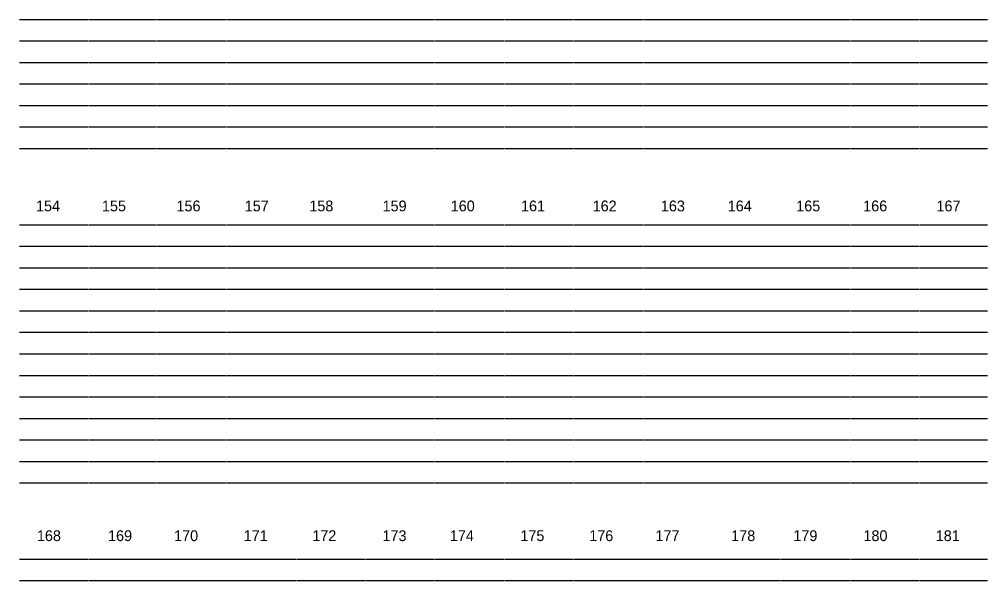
# Model space of a CAD drawing. Extents: x 11193 to 12507, y 10092 to 10555.
# Drawn here: x 11448.5 to 11643.4, y 10207.5 to 10320.5 of the extents above; entities that cross this region are included whole.
import ezdxf

# ---------------------------------------------------------------- set-up
doc = ezdxf.new("R2010")
doc.units = 0
doc.layers.add('Level 2', color=7, linetype='Continuous')

msp = doc.modelspace()

# ---------------------------------------------------------------- linework, layer by layer
at = {"layer": 'Level 2'}
for p, q in [((11448.48, 10320.47), (11462.41, 10320.47)), ((11462.53, 10320.47), (11476.09, 10320.47)), ((11476.2, 10320.47), (11490.17, 10320.47)), ((11490.29, 10320.47), (11504.25, 10320.47)), ((11504.37, 10320.47), (11518.14, 10320.47)), ((11518.25, 10320.47), (11532.02, 10320.47)), ((11532.12, 10320.47), (11546.1, 10320.47)), ((11546.2, 10320.47), (11559.98, 10320.47)), ((11560.08, 10320.47), (11574.07, 10320.47)), ((11574.17, 10320.47), (11587.94, 10320.47)), ((11588.04, 10320.47), (11601.62, 10320.47)), ((11601.72, 10320.47), (11615.7, 10320.47)), ((11615.8, 10320.47), (11629.58, 10320.47)), ((11629.69, 10320.47), (11643.42, 10320.47)), ((11448.48, 10316.13), (11462.41, 10316.13)), ((11462.53, 10316.13), (11476.09, 10316.13)), ((11476.2, 10316.13), (11490.17, 10316.13)), ((11490.29, 10316.13), (11504.25, 10316.13)), ((11504.37, 10316.13), (11518.14, 10316.13)), ((11518.25, 10316.13), (11532.02, 10316.13)), ((11532.12, 10316.13), (11546.1, 10316.13)), ((11546.2, 10316.13), (11559.98, 10316.13)), ((11560.08, 10316.13), (11574.07, 10316.13)), ((11574.17, 10316.13), (11587.94, 10316.13)), ((11588.04, 10316.13), (11601.62, 10316.13)), ((11601.72, 10316.13), (11615.7, 10316.13)), ((11615.8, 10316.13), (11629.58, 10316.13)), ((11629.69, 10316.13), (11643.42, 10316.13)), ((11448.48, 10311.8), (11462.41, 10311.8)), ((11462.53, 10311.8), (11476.09, 10311.8)), ((11476.2, 10311.8), (11490.17, 10311.8)), ((11490.29, 10311.8), (11504.25, 10311.8)), ((11504.37, 10311.8), (11518.14, 10311.8)), ((11518.25, 10311.8), (11532.02, 10311.8)), ((11532.12, 10311.8), (11546.1, 10311.8)), ((11546.2, 10311.8), (11559.98, 10311.8)), ((11560.08, 10311.8), (11574.07, 10311.8)), ((11574.17, 10311.8), (11587.94, 10311.8)), ((11588.04, 10311.8), (11601.62, 10311.8)), ((11601.72, 10311.8), (11615.7, 10311.8)), ((11615.8, 10311.8), (11629.58, 10311.8)), ((11629.69, 10311.8), (11643.42, 10311.8)), ((11448.48, 10307.47), (11462.41, 10307.47)), ((11462.53, 10307.47), (11476.09, 10307.47)), ((11476.2, 10307.47), (11490.17, 10307.47)), ((11490.29, 10307.47), (11504.25, 10307.47)), ((11504.37, 10307.47), (11518.14, 10307.47)), ((11518.25, 10307.47), (11532.02, 10307.47)), ((11532.12, 10307.47), (11546.1, 10307.47)), ((11546.2, 10307.47), (11559.98, 10307.47)), ((11560.08, 10307.47), (11574.07, 10307.47)), ((11574.17, 10307.47), (11587.94, 10307.47)), ((11588.04, 10307.47), (11601.62, 10307.47)), ((11601.72, 10307.47), (11615.7, 10307.47)), ((11615.8, 10307.47), (11629.58, 10307.47)), ((11629.69, 10307.47), (11643.42, 10307.47)), ((11448.48, 10303.14), (11462.41, 10303.14)), ((11462.53, 10303.14), (11476.09, 10303.14)), ((11476.2, 10303.14), (11490.17, 10303.14)), ((11490.29, 10303.14), (11504.25, 10303.14)), ((11504.37, 10303.14), (11518.14, 10303.14)), ((11518.25, 10303.14), (11532.02, 10303.14)), ((11532.12, 10303.14), (11546.1, 10303.14)), ((11546.2, 10303.14), (11559.98, 10303.14)), ((11560.08, 10303.14), (11574.07, 10303.14)), ((11574.17, 10303.14), (11587.94, 10303.14)), ((11588.04, 10303.14), (11601.62, 10303.14)), ((11601.72, 10303.14), (11615.7, 10303.14)), ((11615.8, 10303.14), (11629.58, 10303.14)), ((11629.69, 10303.14), (11643.42, 10303.14)), ((11448.48, 10298.81), (11462.41, 10298.81)), ((11462.53, 10298.81), (11476.09, 10298.81)), ((11476.2, 10298.81), (11490.17, 10298.81)), ((11490.29, 10298.81), (11504.25, 10298.81)), ((11504.37, 10298.81), (11518.14, 10298.81)), ((11518.25, 10298.81), (11532.02, 10298.81)), ((11532.12, 10298.81), (11546.1, 10298.81)), ((11546.2, 10298.81), (11559.98, 10298.81)), ((11560.08, 10298.81), (11574.07, 10298.81)), ((11574.17, 10298.81), (11587.94, 10298.81)), ((11588.04, 10298.81), (11601.62, 10298.81)), ((11601.72, 10298.81), (11615.7, 10298.81)), ((11615.8, 10298.81), (11629.58, 10298.81)), ((11629.69, 10298.81), (11643.42, 10298.81)), ((11448.48, 10294.47), (11462.41, 10294.47)), ((11462.53, 10294.47), (11476.09, 10294.47)), ((11476.2, 10294.47), (11490.17, 10294.47)), ((11490.29, 10294.47), (11504.25, 10294.47)), ((11504.37, 10294.47), (11518.14, 10294.47)), ((11518.25, 10294.47), (11532.02, 10294.47)), ((11532.12, 10294.47), (11546.1, 10294.47)), ((11546.2, 10294.47), (11559.98, 10294.47)), ((11560.08, 10294.47), (11574.07, 10294.47)), ((11574.17, 10294.47), (11587.94, 10294.47)), ((11588.04, 10294.47), (11601.62, 10294.47)), ((11601.72, 10294.47), (11615.7, 10294.47)), ((11615.8, 10294.47), (11629.58, 10294.47)), ((11629.69, 10294.47), (11643.42, 10294.47)), ((11448.48, 10279.14), (11462.41, 10279.14)), ((11462.53, 10279.14), (11476.09, 10279.14)), ((11476.2, 10279.14), (11490.17, 10279.14)), ((11490.29, 10279.14), (11504.25, 10279.14)), ((11504.37, 10279.14), (11518.14, 10279.14)), ((11518.25, 10279.14), (11532.02, 10279.14)), ((11532.12, 10279.14), (11546.1, 10279.14)), ((11546.2, 10279.14), (11559.98, 10279.14)), ((11560.08, 10279.14), (11574.07, 10279.14)), ((11574.17, 10279.14), (11587.94, 10279.14)), ((11588.04, 10279.14), (11601.62, 10279.14)), ((11601.72, 10279.14), (11615.7, 10279.14)), ((11615.8, 10279.14), (11629.58, 10279.14)), ((11629.69, 10279.14), (11643.42, 10279.14)), ((11448.48, 10274.81), (11462.41, 10274.81)), ((11462.53, 10274.81), (11476.09, 10274.81)), ((11476.2, 10274.81), (11490.17, 10274.81)), ((11490.29, 10274.81), (11504.25, 10274.81)), ((11504.37, 10274.81), (11518.14, 10274.81)), ((11518.25, 10274.81), (11532.02, 10274.81)), ((11532.12, 10274.81), (11546.1, 10274.81)), ((11546.2, 10274.81), (11559.98, 10274.81)), ((11560.08, 10274.81), (11574.07, 10274.81)), ((11574.17, 10274.81), (11587.94, 10274.81)), ((11588.04, 10274.81), (11601.62, 10274.81)), ((11601.72, 10274.81), (11615.7, 10274.81)), ((11615.8, 10274.81), (11629.58, 10274.81)), ((11629.69, 10274.81), (11643.42, 10274.81)), ((11448.48, 10270.48), (11462.41, 10270.48)), ((11462.53, 10270.48), (11476.09, 10270.48)), ((11476.2, 10270.48), (11490.17, 10270.48)), ((11490.29, 10270.48), (11504.25, 10270.48)), ((11504.37, 10270.48), (11518.14, 10270.48)), ((11518.25, 10270.48), (11532.02, 10270.48)), ((11532.12, 10270.48), (11546.1, 10270.48)), ((11546.2, 10270.48), (11559.98, 10270.48)), ((11560.08, 10270.48), (11574.07, 10270.48)), ((11574.17, 10270.48), (11587.94, 10270.48)), ((11588.04, 10270.48), (11601.62, 10270.48)), ((11601.72, 10270.48), (11615.7, 10270.48)), ((11615.8, 10270.48), (11629.58, 10270.48)), ((11629.69, 10270.48), (11643.42, 10270.48)), ((11448.48, 10266.14), (11462.41, 10266.14)), ((11462.53, 10266.14), (11476.09, 10266.14)), ((11476.2, 10266.14), (11490.17, 10266.14)), ((11490.29, 10266.14), (11504.25, 10266.14)), ((11504.37, 10266.14), (11518.14, 10266.14)), ((11518.25, 10266.14), (11532.02, 10266.14)), ((11532.12, 10266.14), (11546.1, 10266.14)), ((11546.2, 10266.14), (11559.98, 10266.14)), ((11560.08, 10266.14), (11574.07, 10266.14)), ((11574.17, 10266.14), (11587.94, 10266.14)), ((11588.04, 10266.14), (11601.62, 10266.14)), ((11601.72, 10266.14), (11615.7, 10266.14)), ((11615.8, 10266.14), (11629.58, 10266.14)), ((11629.69, 10266.14), (11643.42, 10266.14)), ((11448.48, 10261.81), (11462.41, 10261.81)), ((11462.53, 10261.81), (11476.09, 10261.81)), ((11476.2, 10261.81), (11490.17, 10261.81)), ((11490.29, 10261.81), (11504.25, 10261.81)), ((11504.37, 10261.81), (11518.14, 10261.81)), ((11518.25, 10261.81), (11532.02, 10261.81)), ((11532.12, 10261.81), (11546.1, 10261.81)), ((11546.2, 10261.81), (11559.98, 10261.81)), ((11560.08, 10261.81), (11574.07, 10261.81)), ((11574.17, 10261.81), (11587.94, 10261.81)), ((11588.04, 10261.81), (11601.62, 10261.81)), ((11601.72, 10261.81), (11615.7, 10261.81)), ((11615.8, 10261.81), (11629.58, 10261.81)), ((11629.69, 10261.81), (11643.42, 10261.81)), ((11448.48, 10257.48), (11462.41, 10257.48)), ((11462.53, 10257.48), (11476.09, 10257.48)), ((11476.2, 10257.48), (11490.17, 10257.48)), ((11490.29, 10257.48), (11504.25, 10257.48)), ((11504.37, 10257.48), (11518.14, 10257.48)), ((11518.25, 10257.48), (11532.02, 10257.48)), ((11532.12, 10257.48), (11546.1, 10257.48)), ((11546.2, 10257.48), (11559.98, 10257.48)), ((11560.08, 10257.48), (11574.07, 10257.48)), ((11574.17, 10257.48), (11587.94, 10257.48)), ((11588.04, 10257.48), (11601.62, 10257.48)), ((11601.72, 10257.48), (11615.7, 10257.48)), ((11615.8, 10257.48), (11629.58, 10257.48)), ((11629.69, 10257.48), (11643.42, 10257.48)), ((11448.48, 10253.15), (11462.41, 10253.15)), ((11462.53, 10253.15), (11476.09, 10253.15)), ((11476.2, 10253.15), (11490.17, 10253.15)), ((11490.29, 10253.15), (11504.25, 10253.15)), ((11504.37, 10253.15), (11518.14, 10253.15)), ((11518.25, 10253.15), (11532.02, 10253.15)), ((11532.12, 10253.15), (11546.1, 10253.15)), ((11546.2, 10253.15), (11559.98, 10253.15)), ((11560.08, 10253.15), (11574.07, 10253.15)), ((11574.17, 10253.15), (11587.94, 10253.15)), ((11588.04, 10253.15), (11601.62, 10253.15)), ((11601.72, 10253.15), (11615.7, 10253.15)), ((11615.8, 10253.15), (11629.58, 10253.15)), ((11629.69, 10253.15), (11643.42, 10253.15)), ((11448.48, 10248.82), (11462.41, 10248.82)), ((11462.53, 10248.82), (11476.09, 10248.82)), ((11476.2, 10248.82), (11490.17, 10248.82)), ((11490.29, 10248.82), (11504.25, 10248.82)), ((11504.37, 10248.82), (11518.14, 10248.82)), ((11518.25, 10248.82), (11532.02, 10248.82)), ((11532.12, 10248.82), (11546.1, 10248.82)), ((11546.2, 10248.82), (11559.98, 10248.82)), ((11560.08, 10248.82), (11574.07, 10248.82)), ((11574.17, 10248.82), (11587.94, 10248.82)), ((11588.04, 10248.82), (11601.62, 10248.82)), ((11601.72, 10248.82), (11615.7, 10248.82)), ((11615.8, 10248.82), (11629.58, 10248.82)), ((11629.69, 10248.82), (11643.42, 10248.82)), ((11448.48, 10244.48), (11462.41, 10244.48)), ((11462.53, 10244.48), (11476.09, 10244.48)), ((11476.2, 10244.48), (11490.17, 10244.48)), ((11490.29, 10244.48), (11504.25, 10244.48)), ((11504.37, 10244.48), (11518.14, 10244.48)), ((11518.25, 10244.48), (11532.02, 10244.48)), ((11532.12, 10244.48), (11546.1, 10244.48)), ((11546.2, 10244.48), (11559.98, 10244.48)), ((11560.08, 10244.48), (11574.07, 10244.48)), ((11574.17, 10244.48), (11587.94, 10244.48)), ((11588.04, 10244.48), (11601.62, 10244.48)), ((11601.72, 10244.48), (11615.7, 10244.48)), ((11615.8, 10244.48), (11629.58, 10244.48)), ((11629.69, 10244.48), (11643.42, 10244.48)), ((11448.48, 10240.15), (11462.41, 10240.15)), ((11462.53, 10240.15), (11476.09, 10240.15)), ((11476.2, 10240.15), (11490.17, 10240.15)), ((11490.29, 10240.15), (11504.25, 10240.15)), ((11504.37, 10240.15), (11518.14, 10240.15)), ((11518.25, 10240.15), (11532.02, 10240.15)), ((11532.12, 10240.15), (11546.1, 10240.15)), ((11546.2, 10240.15), (11559.98, 10240.15)), ((11560.08, 10240.15), (11574.07, 10240.15)), ((11574.17, 10240.15), (11587.94, 10240.15)), ((11588.04, 10240.15), (11601.62, 10240.15)), ((11601.72, 10240.15), (11615.7, 10240.15)), ((11615.8, 10240.15), (11629.58, 10240.15)), ((11629.69, 10240.15), (11643.42, 10240.15)), ((11448.48, 10235.82), (11462.41, 10235.82)), ((11462.53, 10235.82), (11476.09, 10235.82)), ((11476.2, 10235.82), (11490.17, 10235.82)), ((11490.29, 10235.82), (11504.25, 10235.82)), ((11504.37, 10235.82), (11518.14, 10235.82)), ((11518.25, 10235.82), (11532.02, 10235.82)), ((11532.12, 10235.82), (11546.1, 10235.82)), ((11546.2, 10235.82), (11559.98, 10235.82)), ((11560.08, 10235.82), (11574.07, 10235.82)), ((11574.17, 10235.82), (11587.94, 10235.82)), ((11588.04, 10235.82), (11601.62, 10235.82)), ((11601.72, 10235.82), (11615.7, 10235.82)), ((11615.8, 10235.82), (11629.58, 10235.82)), ((11629.69, 10235.82), (11643.42, 10235.82)), ((11448.48, 10231.49), (11462.41, 10231.49)), ((11462.53, 10231.49), (11476.09, 10231.49)), ((11476.2, 10231.49), (11490.17, 10231.49)), ((11490.29, 10231.49), (11504.25, 10231.49)), ((11504.37, 10231.49), (11518.14, 10231.49)), ((11518.25, 10231.49), (11532.02, 10231.49)), ((11532.12, 10231.49), (11546.1, 10231.49)), ((11546.2, 10231.49), (11559.98, 10231.49)), ((11560.08, 10231.49), (11574.07, 10231.49)), ((11574.17, 10231.49), (11587.94, 10231.49)), ((11588.04, 10231.49), (11601.62, 10231.49)), ((11601.72, 10231.49), (11615.7, 10231.49)), ((11615.8, 10231.49), (11629.58, 10231.49)), ((11629.69, 10231.49), (11643.42, 10231.49)), ((11448.48, 10227.16), (11462.41, 10227.16)), ((11462.53, 10227.16), (11476.09, 10227.16)), ((11476.2, 10227.16), (11490.17, 10227.16)), ((11490.29, 10227.16), (11504.25, 10227.16)), ((11504.37, 10227.16), (11518.14, 10227.16)), ((11518.25, 10227.16), (11532.02, 10227.16)), ((11532.12, 10227.16), (11546.1, 10227.16)), ((11546.2, 10227.16), (11559.98, 10227.16)), ((11560.08, 10227.16), (11574.07, 10227.16)), ((11574.17, 10227.16), (11587.94, 10227.16)), ((11588.04, 10227.16), (11601.62, 10227.16)), ((11601.72, 10227.16), (11615.7, 10227.16)), ((11615.8, 10227.16), (11629.58, 10227.16)), ((11629.69, 10227.16), (11643.42, 10227.16)), ((11448.48, 10211.83), (11462.4, 10211.83)), ((11462.5, 10211.83), (11476.08, 10211.83)), ((11476.18, 10211.83), (11490.16, 10211.83)), ((11490.26, 10211.83), (11504.24, 10211.83)), ((11504.35, 10211.83), (11518.12, 10211.83)), ((11518.23, 10211.83), (11532, 10211.83)), ((11532.11, 10211.83), (11546.08, 10211.83)), ((11546.19, 10211.83), (11559.97, 10211.83)), ((11560.08, 10211.83), (11574.05, 10211.83)), ((11574.15, 10211.83), (11587.93, 10211.83)), ((11588.04, 10211.83), (11601.6, 10211.83)), ((11601.71, 10211.83), (11615.68, 10211.83)), ((11615.79, 10211.83), (11629.57, 10211.83)), ((11629.68, 10211.83), (11643.42, 10211.83)), ((11448.48, 10207.5), (11462.4, 10207.5)), ((11462.5, 10207.5), (11476.08, 10207.5)), ((11476.18, 10207.5), (11490.16, 10207.5)), ((11490.26, 10207.5), (11504.24, 10207.5)), ((11504.35, 10207.5), (11518.12, 10207.5)), ((11518.23, 10207.5), (11532, 10207.5)), ((11532.11, 10207.5), (11546.08, 10207.5)), ((11546.19, 10207.5), (11559.97, 10207.5)), ((11560.08, 10207.5), (11574.05, 10207.5)), ((11574.15, 10207.5), (11587.93, 10207.5)), ((11588.04, 10207.5), (11601.6, 10207.5)), ((11601.71, 10207.5), (11615.68, 10207.5)), ((11615.79, 10207.5), (11629.57, 10207.5)), ((11629.68, 10207.5), (11643.42, 10207.5))]:
    msp.add_line(p, q, dxfattribs=at)

# ---------------------------------------------------------------- texts
for s, p in [('154', (11451.82, 10281.83)), ('155', (11465.1, 10281.83)), ('156', (11480.11, 10281.83)), ('157', (11493.85, 10281.83)), ('158', (11506.85, 10281.83)), ('159', (11521.6, 10281.83)), ('160', (11535.32, 10281.83)), ('161', (11549.47, 10281.83)), ('162', (11563.9, 10281.83)), ('163', (11577.63, 10281.83)), ('164', (11591.09, 10281.83)), ('165', (11604.88, 10281.83)), ('166', (11618.36, 10281.83)), ('167', (11633.12, 10281.83)), ('168', (11452.01, 10215.46)), ('169', (11466.33, 10215.46)), ('170', (11479.63, 10215.46)), ('171', (11493.64, 10215.46)), ('172', (11507.45, 10215.46)), ('173', (11521.58, 10215.46)), ('174', (11535.15, 10215.46)), ('175', (11549.34, 10215.46)), ('176', (11563.21, 10215.46)), ('177', (11576.54, 10215.46)), ('178', (11591.79, 10215.46)), ('179', (11604.3, 10215.46)), ('180', (11618.42, 10215.46)), ('181', (11632.97, 10215.46))]:
    msp.add_text(s, height=2.17, dxfattribs=at).set_placement(p)

doc.saveas('drawing.dxf')
